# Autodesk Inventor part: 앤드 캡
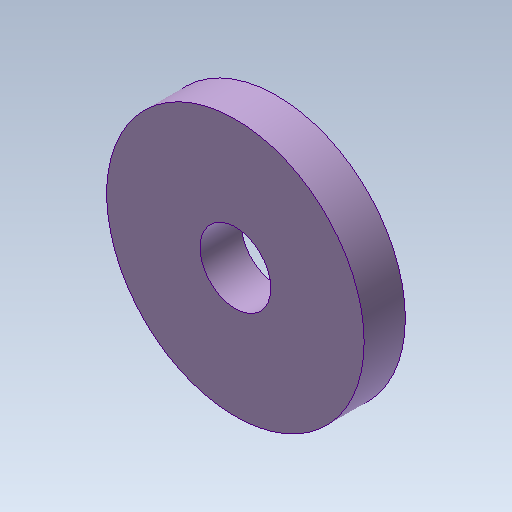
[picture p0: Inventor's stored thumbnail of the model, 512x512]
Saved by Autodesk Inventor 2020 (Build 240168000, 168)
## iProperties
Created: 2024-02
Part Number: 앤드 캡
Material: 강철, 연강
Document SubType Name: Modeling
Designer: mdu-01
Density: 1 g/cm^3
Appearance: 기본값(1)
Author: mdu-01
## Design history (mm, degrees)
sketch "스케치1" dims "d0" = 18.29645 (derived)
  geometry: L1 (19.05, 2.5)-(19.05, -2.5) reference; C1 r 10 at (10.25, 0); C2 r 2.75 at (10.25, 0); A1 r 6.5 centre (10.25, 0) between (16.25, 2.5) and (16.25, -2.5) reference; 2 further points
  constraints: 3 coincident, 2 centre point, 3 other
  dimensions: "d1" = 20 diameter of C1; "d2" = 5.5 diameter of C2
extrude "돌출1" new body sketch "스케치1" distance "d3" = 3.2; taper "d4" = 0 deg
node "솔리드1"
node "참조1"
node "참조2"
